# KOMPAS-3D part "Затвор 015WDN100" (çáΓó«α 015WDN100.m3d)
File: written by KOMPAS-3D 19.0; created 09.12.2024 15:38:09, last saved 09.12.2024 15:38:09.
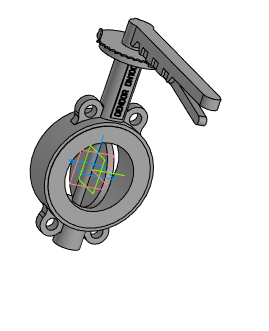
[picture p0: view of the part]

Document properties: Автор: Евгений; Полное имя файла: ..\Затвор 015WDN100.a3d

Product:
- Part/product: Затвор 015WDN100
    Масса: 15.9364

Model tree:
1. Операция без истории:1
